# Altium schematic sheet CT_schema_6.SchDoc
size 372 x 245 mm
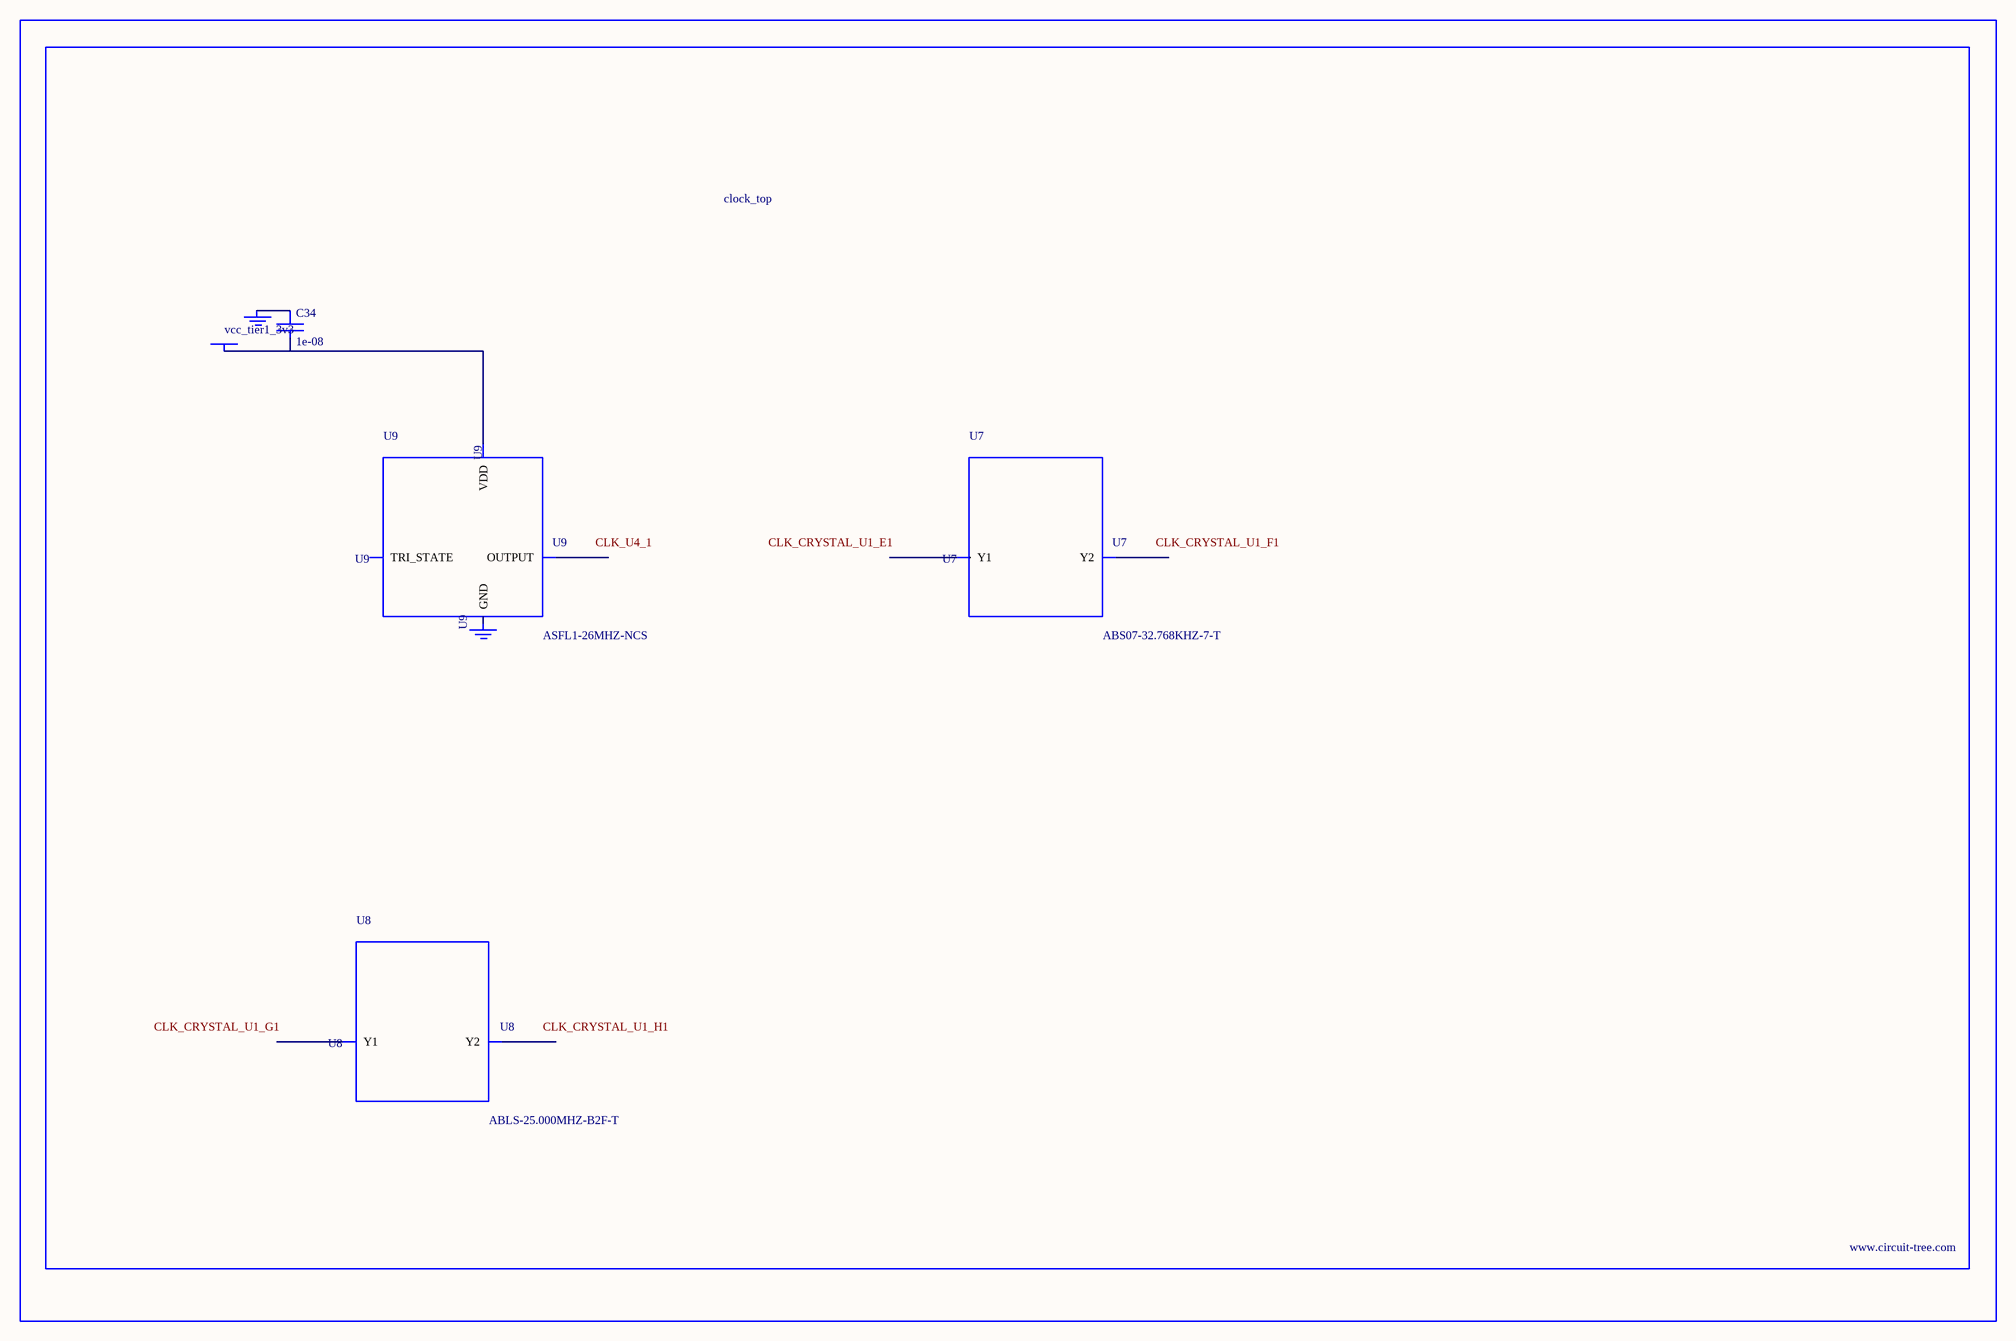
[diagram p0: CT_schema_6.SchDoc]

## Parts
BORDER5  (no value)
C34  1e-08  [C0402]
GND_INSTANCE_5_0  (no value)
GND_INSTANCE_5_1  (no value)
POWER_INSTANCE_5_0  vcc_tier1_3v3
U7  ABS07-32.768KHZ-7-T  [ABS07-32.768KHZ-7-T]
U8  ABLS-25.000MHZ-B2F-T  [ABLS-25.000MHZ-B2F-T]
U9  ASFL1-26MHZ-NCS  [ASFL1]

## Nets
NetC34_1: C34.1 GND_INSTANCE_5_0.0(GND)
NetC34_2: C34.2 POWER_INSTANCE_5_0.0(PWR) U9.4(VDD)

Not connected (* = marked no-connect by the designer): GND_INSTANCE_5_1 0(GND); U7 1(Y1) 2(Y2); U8 1(Y1) 2(Y2); U9 1(TRI_STATE) 2(GND) 3(OUTPUT)

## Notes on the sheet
- Labels drawn without touching a wire or pin: CLK_CRYSTAL_U1_E1, CLK_CRYSTAL_U1_F1, CLK_CRYSTAL_U1_G1, CLK_CRYSTAL_U1_H1, CLK_U4_1

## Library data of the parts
BORDER5 = BORDER_PAGE5
C34 = C0402C103K3RAC
GND_INSTANCE_5_0 GND_INSTANCE_5_1 = GND
POWER_INSTANCE_5_0 = PWR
